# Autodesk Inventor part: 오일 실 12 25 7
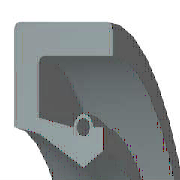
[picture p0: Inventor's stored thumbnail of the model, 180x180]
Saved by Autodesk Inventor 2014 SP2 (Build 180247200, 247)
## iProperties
IsCustomPart: 1
Created: 2012-02
Part Number: 오일 실 12 25 7
Material: 고무
Description: 오일-실
Document SubType Name: Modeling
Standard: KS B 2804
Designer: mduedu
Standards Organization: KS
Language: ko-KR
Size Designation: S - 12 25 7
Categories: <MemberInstance><Categories><Category DisplayName="샤프트 부품" InternalName="7f7aeb1f-a693-4053-b835-cee3144e0d98" Mnemonic="SHFT"><Category DisplayName="실링" Intern
Density: 0.93 g/cm^3
Appearance: 고무 - 검은색 - 버전 1.1
Mass: 1.26338 g
Surface Area: 20.8889 cm^2
Volume: 1.35847 cm^3
Author: mduedu
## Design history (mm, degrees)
revolve "본체" stored, may be unused: angle "d17" = 90 deg
revolve "스프링1" stored, may be unused: angle "d18" = 90 deg
body "Solid1"
sketch "스케치1"
  geometry: L1 (0, 12.5)-(7, 12.5); L2 (7, 12.5)-(7, 11.25); L3 (7, 11.25)-(1.75, 11.25); L4 (0, 12.5)-(0, 8.1); L5 (0, 8.1)-(1.75, 7.75); L6 (1.75, 7.75)-(4.9, 6); L7 (4.9, 6)-(0, 6); L8 (6.3, 6.875)-(6.3, 8.1); L9 (0, 0)-(9.586, 0) reference; L10 (4.9, 6)-(6.3, 6.875); L11 (0, 18)-(0, -3) reference; L12 (-1.917, 0)-(11.503, 0) reference; L13 (4.2, 8.1)-(1.75, 8.59); L14 (1.75, 8.59)-(1.75, 11.25); L15 (6.3, 8.1)-(5.6, 8.1); C1 r 0.455 at (4.9, 8.1); A1 r 0.7 centre (4.9, 8.1) between (5.6, 8.1) and (4.2, 8.1)
  constraints: 26 end point, 5 horizontal alignment, 4 perpendicular, 2 centre point, 2 collinear, 2 horizontal, 2 parallel, 2 point on circle, 2 point on line, 2 vertical alignment, 1 coincident
  dimensions: "d0" = 25 diameter of L1 L9 (= SD2); "d1" = 13.75 diameter of L8.start L9 (= ABDM); "d2" = 1.25 distance of L1.end L2.end (computed from SD); "d3" = 0.91 diameter of C1 (= SPDI); "d4" = 1.4 diameter of A1 (= SPDA); "d5" = 12 diameter of L6.end L9 (= NND); "d6" = 15.5 diameter of L5.end L9 (= TKDM); "d7" = 16.2 diameter of L4.end L9 (= HLDM); "d8" = 4.9 distance from line of C1.centre L4 (= SPDST); "d9" = 6.3 distance between parallel lines of L8 L4 (= SDI); "d10" = 7 distance between parallel lines of L2 L4 (= SWDT); "d12" = 1.75 distance between parallel lines of L14 L4 (= SD)
fillet "모깎기1" dims "d11" = 0.3 (= RR)
other parameters: "SD2" = 25 [user parameter; used in 1 equation term], "SWDT" = 7 [user parameter; used in 1 equation term], "RR" = 0.3 [user parameter; used in 1 equation term], "SD" = 1.75 [user parameter; used in 2 equation terms], "NND" = 12 [user parameter; used in 1 equation term], "SPDA" = 1.4 [user parameter; used in 1 equation term], "SPDI" = 0.91 [user parameter; used in 1 equation term], "TKDM" = 15.5 [user parameter; used in 1 equation term], "HLDM" = 16.2 [user parameter; used in 1 equation term], "ABDM" = 13.75 [user parameter; used in 1 equation term], "SDI" = 6.3 [user parameter; used in 1 equation term], "SPDST" = 4.9 [user parameter; used in 1 equation term], "d13" = 0, "d14" = 0, "d15" = 0, "LAB" = 0.35 [user parameter]
